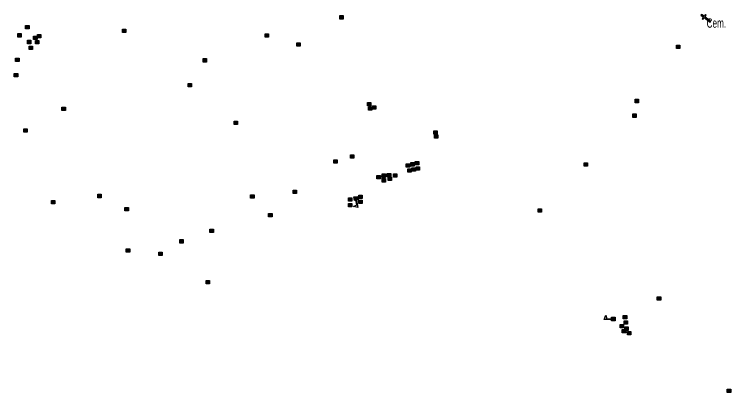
# Model space of a CAD drawing. Extents: x 647.8 to 672.9, y 6929.3 to 6957.3.
# Drawn here: x 654.28 to 660.39, y 6950.63 to 6953.85 of the extents above; entities that cross this region are included whole.
import ezdxf

# ---------------------------------------------------------------- set-up
doc = ezdxf.new("R2010")
doc.units = 0
doc.header["$LTSCALE"] = 0.032
for name, color, linetype, lineweight in [('2', 7, 'Continuous', 25), ('20', 7, 'Continuous', 25), ('4', 7, 'Continuous', 25)]:
    doc.layers.add(name, color=color, linetype=linetype, lineweight=lineweight)
doc.layers.add('61', color=7, linetype='Continuous')

msp = doc.modelspace()

# ---------------------------------------------------------------- hatches: boundary and pattern name
at = {"layer": '2'}
for points in [[(657.0601, 6953.8428), (657.0891, 6953.8428), (657.0891, 6953.8138), (657.0601, 6953.8138)], [(654.3814, 6953.7594), (654.4104, 6953.7594), (654.4104, 6953.7304), (654.3814, 6953.7304)], [(655.2063, 6953.7287), (655.2353, 6953.7287), (655.2353, 6953.6997), (655.2063, 6953.6997)], [(654.3134, 6953.6892), (654.3424, 6953.6892), (654.3424, 6953.6602), (654.3134, 6953.6602)], [(654.4494, 6953.6673), (654.4784, 6953.6673), (654.4784, 6953.6383), (654.4494, 6953.6383)], [(654.4823, 6953.6827), (654.5113, 6953.6827), (654.5113, 6953.6537), (654.4823, 6953.6537)], [(656.4217, 6953.6871), (656.4507, 6953.6871), (656.4507, 6953.6581), (656.4217, 6953.6581)], [(654.3968, 6953.6322), (654.4258, 6953.6322), (654.4258, 6953.6032), (654.3968, 6953.6032)], [(654.4121, 6953.5839), (654.4411, 6953.5839), (654.4411, 6953.5549), (654.4121, 6953.5549)], [(654.4648, 6953.63), (654.4938, 6953.63), (654.4938, 6953.601), (654.4648, 6953.601)], [(656.6937, 6953.6103), (656.7227, 6953.6103), (656.7227, 6953.5813), (656.6937, 6953.5813)], [(659.9297, 6953.5905), (659.9587, 6953.5905), (659.9587, 6953.5615), (659.9297, 6953.5615)], [(654.2959, 6953.4808), (654.3249, 6953.4808), (654.3249, 6953.4518), (654.2959, 6953.4518)], [(655.8952, 6953.4764), (655.9242, 6953.4764), (655.9242, 6953.4474), (655.8952, 6953.4474)], [(654.2849, 6953.3492), (654.3139, 6953.3492), (654.3139, 6953.3202), (654.2849, 6953.3202)], [(655.7657, 6953.2658), (655.7947, 6953.2658), (655.7947, 6953.2368), (655.7657, 6953.2368)], [(657.2949, 6953.1035), (657.3239, 6953.1035), (657.3239, 6953.0745), (657.2949, 6953.0745)], [(659.5765, 6953.1298), (659.6055, 6953.1298), (659.6055, 6953.1008), (659.5765, 6953.1008)], [(654.6908, 6953.064), (654.7198, 6953.064), (654.7198, 6953.035), (654.6908, 6953.035)], [(657.3036, 6953.0662), (657.3326, 6953.0662), (657.3326, 6953.0372), (657.3036, 6953.0372)], [(657.3365, 6953.075), (657.3655, 6953.075), (657.3655, 6953.046), (657.3365, 6953.046)], [(659.5567, 6953.0048), (659.5857, 6953.0048), (659.5857, 6952.9758), (659.5567, 6952.9758)], [(656.1584, 6952.9433), (656.1874, 6952.9433), (656.1874, 6952.9143), (656.1584, 6952.9143)], [(654.3661, 6952.8775), (654.3951, 6952.8775), (654.3951, 6952.8485), (654.3661, 6952.8485)], [(657.8609, 6952.8622), (657.8899, 6952.8622), (657.8899, 6952.8332), (657.8609, 6952.8332)], [(657.8653, 6952.8271), (657.8943, 6952.8271), (657.8943, 6952.7981), (657.8653, 6952.7981)], [(657.0075, 6952.6143), (657.0365, 6952.6143), (657.0365, 6952.5853), (657.0075, 6952.5853)], [(657.1501, 6952.6559), (657.1791, 6952.6559), (657.1791, 6952.6269), (657.1501, 6952.6269)], [(657.6261, 6952.5814), (657.6551, 6952.5814), (657.6551, 6952.5524), (657.6261, 6952.5524)], [(657.6634, 6952.5901), (657.6924, 6952.5901), (657.6924, 6952.5611), (657.6634, 6952.5611)], [(657.6744, 6952.5463), (657.7034, 6952.5463), (657.7034, 6952.5173), (657.6744, 6952.5173)], [(657.7029, 6952.6011), (657.7319, 6952.6011), (657.7319, 6952.5721), (657.7029, 6952.5721)], [(657.7095, 6952.555), (657.7385, 6952.555), (657.7385, 6952.526), (657.7095, 6952.526)], [(659.1421, 6952.5879), (659.1711, 6952.5879), (659.1711, 6952.5589), (659.1421, 6952.5589)], [(657.4199, 6952.4936), (657.4489, 6952.4936), (657.4489, 6952.4646), (657.4199, 6952.4646)], [(657.4638, 6952.498), (657.4928, 6952.498), (657.4928, 6952.469), (657.4638, 6952.469)], [(657.5164, 6952.4958), (657.5454, 6952.4958), (657.5454, 6952.4668), (657.5164, 6952.4668)], [(657.6393, 6952.5375), (657.6683, 6952.5375), (657.6683, 6952.5085), (657.6393, 6952.5085)], [(657.376, 6952.4804), (657.405, 6952.4804), (657.405, 6952.4514), (657.376, 6952.4514)], [(657.4199, 6952.4541), (657.4489, 6952.4541), (657.4489, 6952.4251), (657.4199, 6952.4251)], [(657.4704, 6952.4673), (657.4994, 6952.4673), (657.4994, 6952.4383), (657.4704, 6952.4383)], [(654.9957, 6952.3203), (655.0247, 6952.3203), (655.0247, 6952.2913), (654.9957, 6952.2913)], [(656.2988, 6952.3159), (656.3278, 6952.3159), (656.3278, 6952.2869), (656.2988, 6952.2869)], [(656.6608, 6952.3554), (656.6898, 6952.3554), (656.6898, 6952.3264), (656.6608, 6952.3264)], [(657.2203, 6952.3137), (657.2493, 6952.3137), (657.2493, 6952.2847), (657.2203, 6952.2847)], [(654.6008, 6952.2676), (654.6298, 6952.2676), (654.6298, 6952.2386), (654.6008, 6952.2386)], [(657.1325, 6952.2896), (657.1615, 6952.2896), (657.1615, 6952.2606), (657.1325, 6952.2606)], [(657.1325, 6952.2435), (657.1615, 6952.2435), (657.1615, 6952.2145), (657.1325, 6952.2145)], [(657.2203, 6952.2698), (657.2493, 6952.2698), (657.2493, 6952.2408), (657.2203, 6952.2408)], [(655.2282, 6952.2084), (655.2572, 6952.2084), (655.2572, 6952.1794), (655.2282, 6952.1794)], [(658.7494, 6952.1974), (658.7784, 6952.1974), (658.7784, 6952.1684), (658.7494, 6952.1684)], [(656.4524, 6952.1579), (656.4814, 6952.1579), (656.4814, 6952.1289), (656.4524, 6952.1289)], [(655.9522, 6952.0241), (655.9812, 6952.0241), (655.9812, 6951.9951), (655.9522, 6951.9951)], [(655.6955, 6951.9342), (655.7245, 6951.9342), (655.7245, 6951.9052), (655.6955, 6951.9052)], [(655.2392, 6951.8552), (655.2682, 6951.8552), (655.2682, 6951.8262), (655.2392, 6951.8262)], [(655.5156, 6951.8289), (655.5446, 6951.8289), (655.5446, 6951.7999), (655.5156, 6951.7999)], [(655.9193, 6951.5875), (655.9483, 6951.5875), (655.9483, 6951.5585), (655.9193, 6951.5585)], [(659.7651, 6951.4471), (659.7941, 6951.4471), (659.7941, 6951.4181), (659.7651, 6951.4181)], [(659.4755, 6951.2892), (659.5045, 6951.2892), (659.5045, 6951.2602), (659.4755, 6951.2602)], [(659.4492, 6951.2124), (659.4782, 6951.2124), (659.4782, 6951.1834), (659.4492, 6951.1834)], [(659.4821, 6951.2431), (659.5111, 6951.2431), (659.5111, 6951.2141), (659.4821, 6951.2141)], [(659.4668, 6951.1685), (659.4958, 6951.1685), (659.4958, 6951.1395), (659.4668, 6951.1395)], [(659.4887, 6951.1905), (659.5177, 6951.1905), (659.5177, 6951.1615), (659.4887, 6951.1615)], [(659.5106, 6951.151), (659.5396, 6951.151), (659.5396, 6951.122), (659.5106, 6951.122)], [(660.3618, 6950.6595), (660.3908, 6950.6595), (660.3908, 6950.6305), (660.3618, 6950.6305)]]:
    msp.add_hatch(color=256, dxfattribs=at).paths.add_polyline_path(points)
at = {"layer": '4'}
for points in [[(657.2096, 6952.3023), (657.2143, 6952.2727), (657.1847, 6952.2679), (657.1799, 6952.2975)], [(659.4055, 6951.2424), (659.3755, 6951.2424), (659.3755, 6951.2724), (659.4055, 6951.2724)]]:
    msp.add_hatch(color=256, dxfattribs=at).paths.add_polyline_path(points)

# ---------------------------------------------------------------- linework, layer by layer
at = {"layer": '2'}
for points in [[(657.0601, 6953.8428), (657.0891, 6953.8428), (657.0891, 6953.8138), (657.0601, 6953.8138)], [(654.3814, 6953.7594), (654.4104, 6953.7594), (654.4104, 6953.7304), (654.3814, 6953.7304)], [(655.2063, 6953.7287), (655.2353, 6953.7287), (655.2353, 6953.6997), (655.2063, 6953.6997)], [(654.3134, 6953.6892), (654.3424, 6953.6892), (654.3424, 6953.6602), (654.3134, 6953.6602)], [(654.4494, 6953.6673), (654.4784, 6953.6673), (654.4784, 6953.6383), (654.4494, 6953.6383)], [(654.4823, 6953.6827), (654.5113, 6953.6827), (654.5113, 6953.6537), (654.4823, 6953.6537)], [(656.4217, 6953.6871), (656.4507, 6953.6871), (656.4507, 6953.6581), (656.4217, 6953.6581)], [(654.3968, 6953.6322), (654.4258, 6953.6322), (654.4258, 6953.6032), (654.3968, 6953.6032)], [(654.4121, 6953.5839), (654.4411, 6953.5839), (654.4411, 6953.5549), (654.4121, 6953.5549)], [(654.4648, 6953.63), (654.4938, 6953.63), (654.4938, 6953.601), (654.4648, 6953.601)], [(656.6937, 6953.6103), (656.7227, 6953.6103), (656.7227, 6953.5813), (656.6937, 6953.5813)], [(659.9297, 6953.5905), (659.9587, 6953.5905), (659.9587, 6953.5615), (659.9297, 6953.5615)], [(654.2959, 6953.4808), (654.3249, 6953.4808), (654.3249, 6953.4518), (654.2959, 6953.4518)], [(655.8952, 6953.4764), (655.9242, 6953.4764), (655.9242, 6953.4474), (655.8952, 6953.4474)], [(654.2849, 6953.3492), (654.3139, 6953.3492), (654.3139, 6953.3202), (654.2849, 6953.3202)], [(655.7657, 6953.2658), (655.7947, 6953.2658), (655.7947, 6953.2368), (655.7657, 6953.2368)], [(657.2949, 6953.1035), (657.3239, 6953.1035), (657.3239, 6953.0745), (657.2949, 6953.0745)], [(659.5765, 6953.1298), (659.6055, 6953.1298), (659.6055, 6953.1008), (659.5765, 6953.1008)], [(654.6908, 6953.064), (654.7198, 6953.064), (654.7198, 6953.035), (654.6908, 6953.035)], [(657.3036, 6953.0662), (657.3326, 6953.0662), (657.3326, 6953.0372), (657.3036, 6953.0372)], [(657.3365, 6953.075), (657.3655, 6953.075), (657.3655, 6953.046), (657.3365, 6953.046)], [(659.5567, 6953.0048), (659.5857, 6953.0048), (659.5857, 6952.9758), (659.5567, 6952.9758)], [(656.1584, 6952.9433), (656.1874, 6952.9433), (656.1874, 6952.9143), (656.1584, 6952.9143)], [(654.3661, 6952.8775), (654.3951, 6952.8775), (654.3951, 6952.8485), (654.3661, 6952.8485)], [(657.8609, 6952.8622), (657.8899, 6952.8622), (657.8899, 6952.8332), (657.8609, 6952.8332)], [(657.8653, 6952.8271), (657.8943, 6952.8271), (657.8943, 6952.7981), (657.8653, 6952.7981)], [(657.0075, 6952.6143), (657.0365, 6952.6143), (657.0365, 6952.5853), (657.0075, 6952.5853)], [(657.1501, 6952.6559), (657.1791, 6952.6559), (657.1791, 6952.6269), (657.1501, 6952.6269)], [(657.6261, 6952.5814), (657.6551, 6952.5814), (657.6551, 6952.5524), (657.6261, 6952.5524)], [(657.6634, 6952.5901), (657.6924, 6952.5901), (657.6924, 6952.5611), (657.6634, 6952.5611)], [(657.6744, 6952.5463), (657.7034, 6952.5463), (657.7034, 6952.5173), (657.6744, 6952.5173)], [(657.7029, 6952.6011), (657.7319, 6952.6011), (657.7319, 6952.5721), (657.7029, 6952.5721)], [(657.7095, 6952.555), (657.7385, 6952.555), (657.7385, 6952.526), (657.7095, 6952.526)], [(659.1421, 6952.5879), (659.1711, 6952.5879), (659.1711, 6952.5589), (659.1421, 6952.5589)], [(657.4199, 6952.4936), (657.4489, 6952.4936), (657.4489, 6952.4646), (657.4199, 6952.4646)], [(657.4638, 6952.498), (657.4928, 6952.498), (657.4928, 6952.469), (657.4638, 6952.469)], [(657.5164, 6952.4958), (657.5454, 6952.4958), (657.5454, 6952.4668), (657.5164, 6952.4668)], [(657.6393, 6952.5375), (657.6683, 6952.5375), (657.6683, 6952.5085), (657.6393, 6952.5085)], [(657.376, 6952.4804), (657.405, 6952.4804), (657.405, 6952.4514), (657.376, 6952.4514)], [(657.4199, 6952.4541), (657.4489, 6952.4541), (657.4489, 6952.4251), (657.4199, 6952.4251)], [(657.4704, 6952.4673), (657.4994, 6952.4673), (657.4994, 6952.4383), (657.4704, 6952.4383)], [(654.9957, 6952.3203), (655.0247, 6952.3203), (655.0247, 6952.2913), (654.9957, 6952.2913)], [(656.2988, 6952.3159), (656.3278, 6952.3159), (656.3278, 6952.2869), (656.2988, 6952.2869)], [(656.6608, 6952.3554), (656.6898, 6952.3554), (656.6898, 6952.3264), (656.6608, 6952.3264)], [(657.2203, 6952.3137), (657.2493, 6952.3137), (657.2493, 6952.2847), (657.2203, 6952.2847)], [(654.6008, 6952.2676), (654.6298, 6952.2676), (654.6298, 6952.2386), (654.6008, 6952.2386)], [(657.1325, 6952.2896), (657.1615, 6952.2896), (657.1615, 6952.2606), (657.1325, 6952.2606)], [(657.1325, 6952.2435), (657.1615, 6952.2435), (657.1615, 6952.2145), (657.1325, 6952.2145)], [(657.2203, 6952.2698), (657.2493, 6952.2698), (657.2493, 6952.2408), (657.2203, 6952.2408)], [(655.2282, 6952.2084), (655.2572, 6952.2084), (655.2572, 6952.1794), (655.2282, 6952.1794)], [(658.7494, 6952.1974), (658.7784, 6952.1974), (658.7784, 6952.1684), (658.7494, 6952.1684)], [(656.4524, 6952.1579), (656.4814, 6952.1579), (656.4814, 6952.1289), (656.4524, 6952.1289)], [(655.9522, 6952.0241), (655.9812, 6952.0241), (655.9812, 6951.9951), (655.9522, 6951.9951)], [(655.6955, 6951.9342), (655.7245, 6951.9342), (655.7245, 6951.9052), (655.6955, 6951.9052)], [(655.2392, 6951.8552), (655.2682, 6951.8552), (655.2682, 6951.8262), (655.2392, 6951.8262)], [(655.5156, 6951.8289), (655.5446, 6951.8289), (655.5446, 6951.7999), (655.5156, 6951.7999)], [(655.9193, 6951.5875), (655.9483, 6951.5875), (655.9483, 6951.5585), (655.9193, 6951.5585)], [(659.7651, 6951.4471), (659.7941, 6951.4471), (659.7941, 6951.4181), (659.7651, 6951.4181)], [(659.4755, 6951.2892), (659.5045, 6951.2892), (659.5045, 6951.2602), (659.4755, 6951.2602)], [(659.4492, 6951.2124), (659.4782, 6951.2124), (659.4782, 6951.1834), (659.4492, 6951.1834)], [(659.4821, 6951.2431), (659.5111, 6951.2431), (659.5111, 6951.2141), (659.4821, 6951.2141)], [(659.4668, 6951.1685), (659.4958, 6951.1685), (659.4958, 6951.1395), (659.4668, 6951.1395)], [(659.4887, 6951.1905), (659.5177, 6951.1905), (659.5177, 6951.1615), (659.4887, 6951.1615)], [(659.5106, 6951.151), (659.5396, 6951.151), (659.5396, 6951.122), (659.5106, 6951.122)], [(660.3618, 6950.6595), (660.3908, 6950.6595), (660.3908, 6950.6305), (660.3618, 6950.6305)]]:
    msp.add_lwpolyline(points, close=True, dxfattribs=at)
at = {"layer": '20'}
for points in [[(660.1636, 6953.837), (660.1411, 6953.8537), (660.1363, 6953.8473), (660.1588, 6953.8306)], [(660.1588, 6953.8306), (660.1469, 6953.8145), (660.1537, 6953.8095), (660.1656, 6953.8255), (660.2166, 6953.7876)], [(660.1704, 6953.8319), (660.1823, 6953.848), (660.1755, 6953.853), (660.1636, 6953.837)], [(660.2166, 6953.7876), (660.2213, 6953.794), (660.1704, 6953.8319)]]:
    msp.add_lwpolyline(points, dxfattribs=at)
at = {"layer": '4'}
for p, q in [((657.202, 6952.2707), (657.1971, 6952.2699)), ((659.3755, 6951.2549), (659.3755, 6951.2599))]:
    msp.add_line(p, q, dxfattribs=at)
for points in [[(657.2096, 6952.3023), (657.2143, 6952.2727), (657.1847, 6952.2679), (657.1799, 6952.2975)], [(657.202, 6952.2707), (657.212, 6952.209), (657.1754, 6952.2158), (657.2034, 6952.2309), (657.1971, 6952.2699)], [(659.3755, 6951.2549), (659.313, 6951.2547), (659.3254, 6951.2897), (659.336, 6951.2598), (659.3755, 6951.2599)], [(659.4055, 6951.2424), (659.3755, 6951.2424), (659.3755, 6951.2724), (659.4055, 6951.2724)]]:
    msp.add_lwpolyline(points, close=True, dxfattribs=at)

# ---------------------------------------------------------------- texts
at = {"layer": '61', "width": 0.65}
msp.add_text('Cem.', height=0.08, dxfattribs=at).set_placement((660.1858, 6953.7394))

doc.saveas('drawing.dxf')
